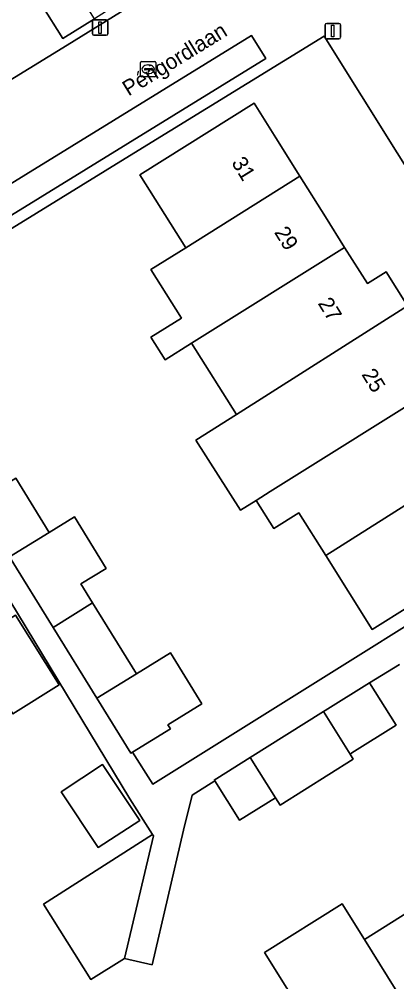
# Model space of a CAD drawing. Extents: x 157767 to 159172, y 387839 to 389425.
# Drawn here: x 158345.5 to 158369.9, y 388137.7 to 388199.8 of the extents above; entities that cross this region are included whole.
import ezdxf

# ---------------------------------------------------------------- set-up
doc = ezdxf.new("R2010")
doc.units = 0
for name, color, linetype in [('IMGEO_Erf', 7, 'Continuous'), ('IMGEO_Kolk', 7, 'Continuous'), ('IMGEO_Lichtmast', 7, 'Continuous'), ('IMGEO_Muur', 7, 'Continuous'), ('IMGEO_Openbare_ruimte_label', 7, 'Continuous'), ('IMGEO_Pand', 7, 'Continuous'), ('IMGEO_Pand_nummerreeks', 7, 'Continuous'), ('IMGEO_Parkeervlak_open', 7, 'Continuous'), ('IMGEO_Rijbaan_lokaal_open', 7, 'Continuous'), ('IMGEO_Voetpad_open', 7, 'Continuous')]:
    doc.layers.add(name, color=color, linetype=linetype)

msp = doc.modelspace()

# ---------------------------------------------------------------- linework, layer by layer
at = {"layer": 'IMGEO_Erf'}
for points in [[(158349.497, 388205.302), (158352.203, 388200.974), (158350.367, 388199.826), (158348.327, 388198.55), (158345.621, 388202.878), (158347.67, 388204.159)], [(158365.167, 388198.706), (158352.615, 388190.965), (158339.034, 388182.597), (158342.746, 388176.574), (158344.937, 388173.02), (158341.361, 388170.817), (158342.735, 388168.588), (158345.292, 388170.164), (158347.446, 388166.668), (158349.073, 388167.671), (158351.12, 388164.35), (158349.493, 388163.347), (158350.241, 388162.135), (158353.069, 388157.546), (158355.265, 388158.899), (158357.294, 388155.608), (158355.098, 388154.254), (158355.258, 388153.995), (158352.825, 388152.496), (158354.129, 388150.416), (158383.764, 388168.963), (158383.379, 388169.579), (158381.815, 388172.081)], [(158345.095, 388154.958), (158342.281, 388159.457), (158345.275, 388161.329), (158348.089, 388156.83)], [(158348.218, 388149.928), (158350.885, 388151.698), (158353.282, 388148.084), (158350.604, 388146.331)]]:
    msp.add_lwpolyline(points, close=True, dxfattribs=at)
for points in [[(158342.746, 388194.533), (158348.606, 388198.107), (158352.487, 388200.522)], [(158370.732, 388161.959), (158368.264, 388160.41), (158365.273, 388165.174), (158363.543, 388167.931), (158361.926, 388166.916), (158360.781, 388168.739), (158359.778, 388168.111), (158356.909, 388172.63), (158359.517, 388174.286), (158356.63, 388178.887), (158354.921, 388177.811), (158354.007, 388179.267), (158355.974, 388180.502), (158354.01, 388183.631), (158356.247, 388185.035), (158353.291, 388189.745), (158360.657, 388194.368), (158362.055, 388192.14), (158363.613, 388189.658), (158365.255, 388187.041), (158366.494, 388185.067), (158367.963, 388182.726), (158369.175, 388183.487), (158370.552, 388181.294)], [(158352.303, 388139.169), (158350.141, 388137.811), (158347.087, 388142.674), (158354.112, 388147.172), (158352.638, 388149.483), (158342.348, 388166.462)], [(158370.028, 388158.152), (158368.095, 388156.973), (158369.816, 388154.23), (158366.955, 388152.435), (158366.843, 388152.365), (158367.051, 388152.035), (158362.33, 388149.073), (158362.034, 388149.546), (158359.71, 388148.089), (158358.116, 388150.629), (158356.667, 388149.714), (158356.101, 388147.452), (158354.084, 388138.756), (158352.303, 388139.169)], [(158362.775, 388137.268), (158361.338, 388139.558), (158366.333, 388142.692), (158367.77, 388140.402), (158372.598, 388143.43)]]:
    msp.add_lwpolyline(points, dxfattribs=at)
at = {"layer": 'IMGEO_Kolk'}
for p, q in [((158353.327, 388196.137), (158353.327, 388196.989)), ((158353.402, 388197.063), (158354.254, 388197.063)), ((158353.815, 388196.843), (158353.84, 388196.843)), ((158354.328, 388196.989), (158354.328, 388196.137)), ((158353.586, 388196.557), (158353.586, 388196.569)), ((158354.024, 388196.52), (158353.626, 388196.52)), ((158353.629, 388196.606), (158354.027, 388196.606)), ((158353.838, 388196.283), (158353.813, 388196.283)), ((158354.07, 388196.569), (158354.07, 388196.557)), ((158354.254, 388196.063), (158353.402, 388196.063))]:
    msp.add_line(p, q, dxfattribs=at)
for points in [[(158353.327, 388196.137), (158353.327, 388196.989)], [(158353.402, 388197.063), (158354.254, 388197.063)], [(158354.328, 388196.989), (158354.328, 388196.137)], [(158354.254, 388196.063), (158353.402, 388196.063)]]:
    msp.add_lwpolyline(points, dxfattribs=at)
for centre, radius, start, end in [((158353.404, 388196.987), 0.0765, 91.55205, 178.44795), ((158353.404, 388196.987), 0.0765, 91.55205, 178.44795), ((158354.252, 388196.987), 0.0765, 1.55205, 88.44795), ((158354.252, 388196.987), 0.0765, 1.55205, 88.44795), ((158353.626, 388196.566), 0.0403, 85.87752, 175.75265), ((158353.623, 388196.556), 0.0366, 178.93798, 274.71019), ((158354.027, 388196.563), 0.043, 264.86636, 352.45326), ((158354.031, 388196.568), 0.0386, 1.73085, 96.63898), ((158353.404, 388196.139), 0.0765, 181.55205, 268.44795), ((158353.404, 388196.139), 0.0765, 181.55205, 268.44795), ((158354.252, 388196.139), 0.0765, 271.55205, 358.44795), ((158354.252, 388196.139), 0.0765, 271.55205, 358.44795)]:
    msp.add_arc(centre, radius, start, end, dxfattribs=at)
for centre, major_axis, ratio, start_param, end_param in [((158353.814, 388196.563), (-0.387, 0.002), 0.722429, 4.712389, 7.853982), ((158353.839, 388196.563), (-0.39, 0.002), 0.717154, 1.570796, 4.712389)]:
    msp.add_ellipse(centre, major_axis=major_axis, ratio=ratio, start_param=start_param, end_param=end_param, dxfattribs=at)
at = {"layer": 'IMGEO_Lichtmast'}
for p, q in [((158350.235, 388198.853), (158350.235, 388199.653)), ((158350.235, 388199.653), (158350.235, 388198.853)), ((158350.335, 388199.753), (158351.125, 388199.753)), ((158351.125, 388199.753), (158350.335, 388199.753)), ((158351.225, 388199.653), (158351.225, 388198.853)), ((158351.225, 388198.853), (158351.225, 388199.653)), ((158365.237, 388198.625), (158365.237, 388199.425)), ((158365.237, 388199.425), (158365.237, 388198.625)), ((158365.337, 388199.525), (158366.127, 388199.525)), ((158366.127, 388199.525), (158365.337, 388199.525)), ((158366.227, 388199.425), (158366.227, 388198.625)), ((158366.227, 388198.625), (158366.227, 388199.425)), ((158351.125, 388198.753), (158350.335, 388198.753)), ((158350.335, 388198.753), (158351.125, 388198.753)), ((158366.127, 388198.525), (158365.337, 388198.525)), ((158365.337, 388198.525), (158366.127, 388198.525))]:
    msp.add_line(p, q, dxfattribs=at)
for points in [[(158350.655, 388199.628), (158350.805, 388199.628), (158350.805, 388198.878), (158350.655, 388198.878), (158350.655, 388199.628)], [(158365.657, 388199.4), (158365.807, 388199.4), (158365.807, 388198.65), (158365.657, 388198.65), (158365.657, 388199.4)]]:
    msp.add_lwpolyline(points, dxfattribs=at)
for centre, start, end in [((158350.335, 388199.653), 90, 180), ((158350.335, 388199.653), 90, 180), ((158351.125, 388199.653), 0, 90), ((158351.125, 388199.653), 360, 90), ((158365.337, 388199.425), 90, 180), ((158365.337, 388199.425), 90, 180), ((158366.127, 388199.425), 0, 90), ((158366.127, 388199.425), 360, 90), ((158350.335, 388198.853), 180, 270), ((158350.335, 388198.853), 180, 270), ((158351.125, 388198.853), 270, 0), ((158351.125, 388198.853), 270, 0), ((158365.337, 388198.625), 180, 270), ((158365.337, 388198.625), 180, 270), ((158366.127, 388198.625), 270, 0), ((158366.127, 388198.625), 270, 0)]:
    msp.add_arc(centre, 0.1, start, end, dxfattribs=at)
at = {"layer": 'IMGEO_Muur'}
msp.add_lwpolyline([(158352.615, 388190.965), (158339.034, 388182.597)], dxfattribs=at)
at = {"layer": 'IMGEO_Pand'}
for points in [[(158350.367, 388199.826), (158347.67, 388204.159), (158345.621, 388202.878), (158348.327, 388198.55)], [(158356.247, 388185.035), (158363.613, 388189.658), (158362.055, 388192.14), (158360.657, 388194.368), (158353.291, 388189.745)], [(158356.247, 388185.035), (158354.01, 388183.631), (158355.974, 388180.502), (158354.007, 388179.267), (158354.921, 388177.811), (158356.63, 388178.887), (158366.494, 388185.067), (158365.255, 388187.041), (158363.613, 388189.658)], [(158370.552, 388181.294), (158369.175, 388183.487), (158367.963, 388182.726), (158366.494, 388185.067), (158356.63, 388178.887), (158359.517, 388174.286)], [(158372.239, 388175.915), (158370.728, 388178.322), (158371.94, 388179.083), (158370.552, 388181.294), (158359.517, 388174.286), (158356.909, 388172.63), (158359.778, 388168.111), (158360.781, 388168.739), (158361.686, 388169.306), (158362.373, 388169.736)], [(158376.293, 388172.15), (158374.939, 388174.306), (158373.727, 388173.545), (158372.239, 388175.915), (158362.373, 388169.736), (158361.686, 388169.306), (158360.781, 388168.739), (158361.926, 388166.916), (158363.543, 388167.931), (158365.273, 388165.174)], [(158378.097, 388166.582), (158379.311, 388167.344), (158377.905, 388169.584), (158376.293, 388172.15), (158365.273, 388165.174), (158368.264, 388160.41), (158370.732, 388161.959), (158373.863, 388163.924)], [(158342.735, 388168.588), (158344.889, 388165.093), (158347.446, 388166.668), (158345.292, 388170.164)], [(158347.446, 388166.668), (158344.889, 388165.093), (158347.695, 388160.541), (158350.241, 388162.135), (158349.493, 388163.347), (158351.12, 388164.35), (158349.073, 388167.671)], [(158350.241, 388162.135), (158347.695, 388160.541), (158350.513, 388155.97), (158353.069, 388157.546)], [(158348.089, 388156.83), (158345.275, 388161.329), (158342.281, 388159.457), (158345.095, 388154.958)], [(158353.069, 388157.546), (158350.513, 388155.97), (158352.701, 388152.42), (158352.825, 388152.496), (158355.258, 388153.995), (158355.098, 388154.254), (158357.294, 388155.608), (158355.265, 388158.899)], [(158368.095, 388156.973), (158365.234, 388155.178), (158365.122, 388155.108), (158366.843, 388152.365), (158366.955, 388152.435), (158369.816, 388154.23)], [(158366.843, 388152.365), (158365.122, 388155.108), (158360.402, 388152.147), (158362.034, 388149.546), (158362.33, 388149.073), (158367.051, 388152.035)], [(158362.034, 388149.546), (158360.402, 388152.147), (158358.252, 388150.798), (158358.079, 388150.689), (158358.116, 388150.629), (158359.71, 388148.089)], [(158348.218, 388149.928), (158350.604, 388146.331), (158353.282, 388148.084), (158350.885, 388151.698)], [(158354.179, 388147.082), (158354.112, 388147.172), (158347.087, 388142.674), (158350.141, 388137.811), (158352.303, 388139.169)], [(158372.331, 388133.064), (158375.157, 388134.833), (158375.682, 388135.162), (158376.762, 388133.438), (158376.236, 388133.109), (158376.38, 388132.88), (158378.348, 388134.112), (158372.598, 388143.43), (158367.77, 388140.402)], [(158372.331, 388133.064), (158367.77, 388140.402), (158366.333, 388142.692), (158361.338, 388139.558), (158362.775, 388137.268), (158368.545, 388128.049), (158367.804, 388127.623), (158371.859, 388120.98), (158373.127, 388118.954), (158375.996, 388120.749), (158373.314, 388125.035), (158370.552, 388129.449), (158370.027, 388129.121), (158368.902, 388130.918), (158369.427, 388131.246)]]:
    msp.add_lwpolyline(points, close=True, dxfattribs=at)
at = {"layer": 'IMGEO_Parkeervlak_open'}
msp.add_lwpolyline([(158340.911, 388184.618), (158361.412, 388197.254), (158360.492, 388198.747), (158339.992, 388186.111)], close=True, dxfattribs=at)
at = {"layer": 'IMGEO_Rijbaan_lokaal_open'}
for points in [[(158378.07, 388214.12), (158375.84, 388217.622), (158373.677, 388216.222), (158354.496, 388203.976), (158355.501, 388202.324), (158355.385, 388202.255), (158352.487, 388200.522), (158348.606, 388198.107), (158342.746, 388194.533)], [(158339.034, 388182.597), (158352.615, 388190.965), (158365.167, 388198.706), (158381.815, 388172.081), (158383.379, 388169.579), (158383.764, 388168.963), (158384.722, 388167.431), (158392.121, 388155.599), (158392.004, 388155.561), (158397.843, 388146.23), (158397.783, 388146.192), (158400.431, 388141.967), (158403.083, 388137.736), (158403.861, 388136.639)]]:
    msp.add_lwpolyline(points, dxfattribs=at)
msp.add_lwpolyline([(158340.911, 388184.618), (158339.992, 388186.111), (158360.492, 388198.747), (158361.412, 388197.254)], close=True, dxfattribs=at)
at = {"layer": 'IMGEO_Voetpad_open'}
for points in [[(158383.764, 388168.963), (158354.129, 388150.416), (158352.825, 388152.496), (158352.701, 388152.42), (158350.513, 388155.97), (158347.695, 388160.541), (158344.889, 388165.093)], [(158342.348, 388166.462), (158352.638, 388149.483), (158354.112, 388147.172), (158354.179, 388147.082), (158352.303, 388139.169), (158354.084, 388138.756), (158356.101, 388147.452), (158356.667, 388149.714), (158358.116, 388150.629), (158358.079, 388150.689), (158358.252, 388150.798), (158360.402, 388152.147), (158365.122, 388155.108), (158365.234, 388155.178), (158368.095, 388156.973), (158370.028, 388158.152)]]:
    msp.add_lwpolyline(points, dxfattribs=at)

# ---------------------------------------------------------------- texts
at = {"layer": 'IMGEO_Openbare_ruimte_label'}
msp.add_text('Périgordlaan', height=1, rotation=31.67132, dxfattribs=at).set_placement((158352.563, 388194.799))
at = {"layer": 'IMGEO_Pand_nummerreeks'}
for s, rotation, p in [('31', 301.53927, (158359.17, 388190.53)), ('29', 301.53927, (158361.927, 388186.039)), ('27', 301.53927, (158364.742, 388181.453)), ('25', 301.54112, (158367.557, 388176.866))]:
    msp.add_text(s, height=1, rotation=rotation, dxfattribs=at).set_placement(p)

doc.saveas('drawing.dxf')
